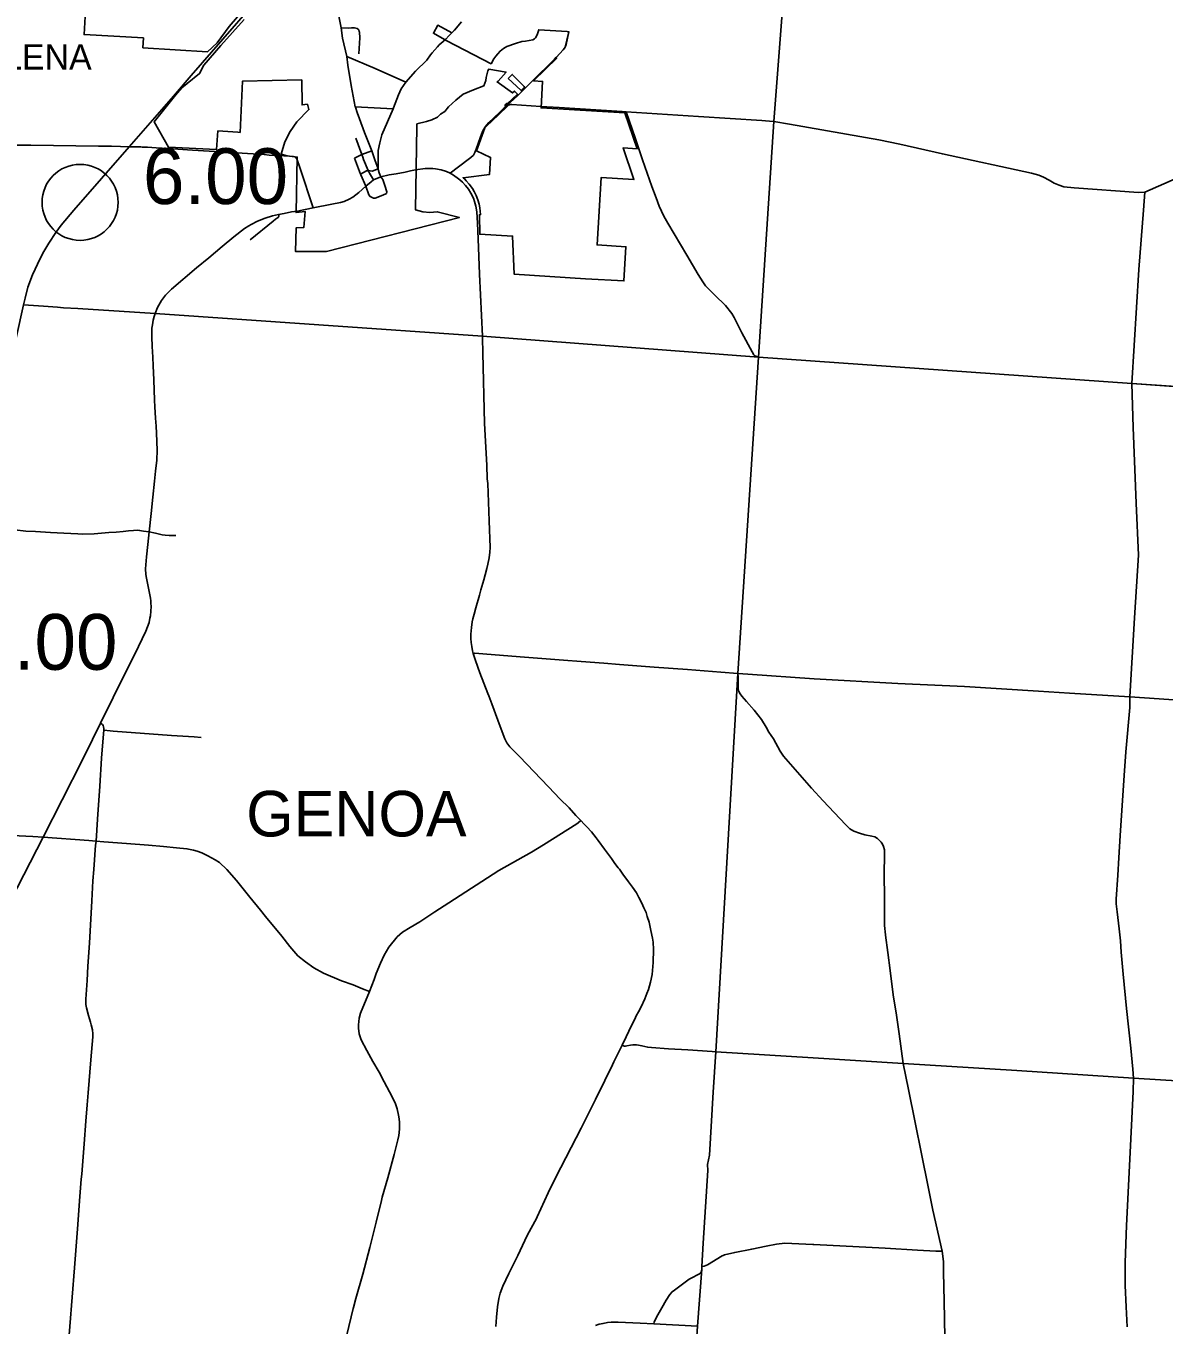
# Model space of a CAD drawing. Extents: x 1597222 to 1925846, y 496284 to 911751.
# Drawn here: x 1855559 to 1878005, y 784412 to 810051 of the extents above; entities that cross this region are included whole.
import ezdxf

# ---------------------------------------------------------------- set-up
doc = ezdxf.new("R2010")
doc.units = 0
for name, color, linetype in [('Default', 7, 'Continuous'), ('GM_X_City_Street', 7, 'Continuous'), ('GM_X_Corporation', 7, 'Continuous'), ('GM_X_Corporation_Text', 7, 'Continuous'), ('GM_X_County_Road', 7, 'Continuous'), ('GM_X_State_Route', 7, 'Continuous'), ('GM_X_Township', 7, 'Continuous'), ('GM_X_Township_Road', 7, 'Continuous'), ('GM_X_Township_Text', 7, 'Continuous')]:
    doc.layers.add(name, color=color, linetype=linetype)

msp = doc.modelspace()

# ---------------------------------------------------------------- linework, layer by layer
at = {"layer": 'Default'}
msp.add_circle((1856626, 806570), 750, dxfattribs=at)
at = {"layer": 'GM_X_City_Street'}
for points in [[(1862504, 807234), (1862441, 807407), (1862377, 807590), (1862238, 807946), (1862134, 808217), (1862091, 808342), (1862056, 808446), (1862054, 808456), (1861975, 808879), (1861910, 809276), (1861885, 809449), (1861803, 809811), (1861778, 810016), (1861699, 810418), (1861546, 811089), (1861463, 811523), (1861444, 811686), (1861392, 811897), (1861379, 812013)], [(1861778, 810016), (1861916, 810011), (1861980, 810012), (1862038, 810014), (1862092, 810003), (1862124, 809974), (1862131, 809944)], [(1862131, 809944), (1862131, 809942), (1862135, 809926), (1862141, 809820), (1862122, 809501)], [(1863675, 809639), (1863707, 809676), (1863789, 809745)], [(1861885, 809449), (1862443, 809212), (1863053, 808941)], [(1862505, 807272), (1862507, 807365), (1862505, 807463), (1862505, 807594), (1862537, 807743), (1862576, 807905), (1862799, 808414), (1862809, 808436), (1862905, 808695), (1862961, 808813), (1863053, 808941), (1863243, 809157), (1863465, 809379), (1863540, 809479)], [(1863540, 809479), (1863570, 809518), (1863675, 809639)], [(1865037, 808477), (1865260, 808682), (1865416, 808836), (1865533, 808954), (1865986, 809398), (1866019, 809433)], [(1862054, 808456), (1862799, 808414)], [(1865037, 808477), (1865069, 808490), (1865093, 808495), (1865114, 808499), (1865142, 808499), (1865716, 808463)], [(1862200, 807464), (1862183, 807513), (1862063, 807839)], [(1860865, 807468), (1860904, 807428), (1860965, 807236), (1861221, 806463)], [(1862038, 807445), (1862183, 807513), (1862377, 807590)], [(1862160, 807115), (1862155, 807127), (1862038, 807445)], [(1862337, 807144), (1862308, 807196), (1862215, 807419), (1862200, 807464)], [(1862155, 807127), (1862275, 807193), (1862300, 807195)], [(1862265, 806887), (1862160, 807115)], [(1862300, 807195), (1862308, 807196), (1862390, 807184), (1862504, 807234)], [(1862411, 807014), (1862337, 807144)], [(1862557, 807072), (1862524, 807153), (1862510, 807198), (1862504, 807234), (1862505, 807272)], [(1863145, 807190), (1863040, 807169), (1862861, 807136), (1862725, 807110), (1862557, 807072)], [(1861065, 806429), (1861221, 806463), (1861591, 806531), (1861760, 806564), (1861833, 806590), (1861930, 806630), (1862004, 806672), (1862127, 806763), (1862265, 806887), (1862364, 806976), (1862411, 807014), (1862557, 807072)], [(1862265, 806887), (1862322, 806718), (1862345, 806686), (1862414, 806654), (1862446, 806655), (1862598, 806709), (1862668, 806748)], [(1862668, 806748), (1862673, 806777), (1862638, 806904), (1862596, 807019), (1862557, 807072)]]:
    msp.add_lwpolyline(points, dxfattribs=at)
at = {"layer": 'GM_X_Corporation'}
for points in [[(1859933, 810468), (1859566, 810043), (1859327, 809721), (1859138, 809540), (1857865, 809621), (1857876, 809816), (1856704, 809881), (1856773, 811076)], [(1864151, 810133), (1864012, 809966), (1863958, 809914), (1863680, 810064), (1863595, 809906), (1863859, 809760), (1864733, 809304), (1864786, 809405), (1864823, 809458), (1864864, 809499), (1864909, 809555), (1864976, 809609), (1865042, 809648), (1865212, 809706), (1865339, 809742), (1865409, 809752), (1865553, 809778), (1865590, 809795), (1865610, 809820), (1865642, 809877), (1865672, 809975), (1866230, 809941), (1866265, 809936), (1866212, 809686), (1866193, 809633), (1866180, 809613), (1866156, 809577), (1866016, 809430), (1866027, 809418), (1865570, 808968), (1865749, 808958), (1865718, 808434), (1867372, 808337), (1867616, 807629), (1867336, 807644), (1867551, 807021), (1866904, 807063), (1866822, 805729), (1867392, 805693), (1867351, 805018), (1866597, 805063), (1865185, 805154), (1865155, 805904), (1864509, 805942), (1864501, 806327), (1864526, 806328), (1864512, 806460), (1864496, 806536), (1864471, 806620), (1864437, 806705), (1864397, 806785), (1864365, 806841), (1864301, 806929), (1864242, 806997), (1864212, 807027), (1864179, 807057), (1864703, 807122), (1864724, 807458), (1864445, 807587), (1864609, 808041), (1864644, 808074), (1864880, 808299), (1865062, 808472), (1865032, 808472), (1865006, 808488), (1865043, 808523), (1865057, 808523), (1865255, 808704), (1865245, 808714), (1865194, 808766), (1865155, 808731), (1864852, 808948), (1864871, 808960), (1865028, 809140), (1864686, 809196), (1864670, 809164), (1864633, 809031), (1864626, 808978), (1864590, 808873), (1864383, 808793), (1864180, 808703), (1864036, 808584), (1863894, 808456), (1863817, 808362), (1863732, 808311), (1863676, 808251), (1863563, 808196), (1863459, 808169), (1863269, 808119), (1863271, 808069), (1863240, 806424), (1863386, 806382), (1863526, 806367), (1863669, 806383), (1864106, 806273), (1861485, 805600), (1860876, 805597), (1860888, 806070), (1861038, 806073), (1861068, 806389), (1860885, 806368), (1860908, 807463), (1860893, 807463), (1860807, 807478), (1860713, 807490), (1860590, 807519), (1860665, 807762), (1860767, 807971), (1860900, 808159), (1861139, 808401), (1861111, 808506), (1861004, 808492), (1860999, 808987), (1859829, 808961), (1859781, 807951), (1859738, 807954), (1859344, 807980), (1859316, 807611), (1858367, 807661), (1858090, 808159), (1858507, 808685), (1858634, 808831), (1858740, 808916), (1858983, 809113), (1859065, 809276), (1859404, 809666), (1859863, 810176)]]:
    msp.add_lwpolyline(points, dxfattribs=at)
msp.add_lwpolyline([(1865072, 809017), (1865316, 808784), (1865324, 808776), (1865394, 808844), (1865384, 808855), (1865149, 809094)], close=True, dxfattribs=at)
at = {"layer": 'GM_X_County_Road'}
for points in [[(1863902, 809854), (1863958, 809914), (1864113, 810086)], [(1863789, 809745), (1863841, 809789), (1863902, 809854)], [(1863927, 807149), (1864283, 807418), (1864334, 807453), (1864387, 807502), (1864414, 807554), (1864439, 807622), (1864484, 807753), (1864542, 807914), (1864570, 807984), (1864606, 808050), (1864642, 808096), (1864687, 808146), (1864789, 808239), (1864902, 808347), (1864988, 808433), (1865037, 808477)], [(1865716, 808463), (1866076, 808441), (1867317, 808363), (1867396, 808359), (1868821, 808266), (1870074, 808188), (1870293, 808165)], [(1867396, 808359), (1867578, 807822), (1867722, 807411), (1867905, 806886), (1867988, 806661), (1868047, 806496), (1868091, 806398), (1868141, 806295), (1868218, 806162), (1868595, 805529), (1868820, 805149), (1868910, 805003), (1868961, 804924), (1869020, 804860), (1869146, 804736), (1869355, 804533), (1869481, 804376), (1869529, 804297), (1869678, 803996), (1869885, 803620), (1869914, 803562), (1869930, 803545)], [(1870293, 808165), (1870309, 808163), (1870615, 808110), (1872380, 807804), (1872796, 807716), (1873633, 807525), (1875394, 807147), (1875535, 807109), (1875625, 807069), (1875741, 807006), (1875837, 806950), (1875938, 806910), (1876028, 806878), (1876232, 806859), (1877504, 806767), (1877627, 806773), (1878001, 806934), (1879588, 807637)], [(1863927, 807149), (1863854, 807181), (1863750, 807215), (1863635, 807231), (1863584, 807238), (1863480, 807241), (1863432, 807239), (1863243, 807210), (1863145, 807190)], [(1864561, 803891), (1864561, 803926), (1864503, 805153), (1864476, 805850), (1864464, 806156), (1864453, 806381), (1864432, 806497), (1864406, 806587), (1864383, 806653), (1864335, 806753), (1864289, 806830), (1864225, 806905), (1864168, 806969), (1864116, 807017), (1864089, 807036), (1863994, 807108), (1863927, 807149)], [(1877369, 802994), (1877508, 805242), (1877600, 806419), (1877627, 806773)], [(1858107, 804378), (1858154, 804496), (1858234, 804633), (1858313, 804738), (1858376, 804801), (1858430, 804854), (1858924, 805276), (1859165, 805478), (1859431, 805702), (1859655, 805890), (1859866, 806052), (1859951, 806106), (1860001, 806134), (1860128, 806199), (1860275, 806259), (1860424, 806303), (1860542, 806330), (1860650, 806352), (1860797, 806382), (1860914, 806399), (1861033, 806421), (1861065, 806429)], [(1860542, 806330), (1860547, 806309), (1860546, 806295), (1860544, 806288), (1860541, 806283), (1860532, 806274), (1860517, 806262), (1860480, 806237), (1860436, 806200), (1859981, 805831)], [(1857028, 796294), (1857277, 796797), (1857775, 797801), (1857924, 798107), (1857985, 798279), (1858004, 798364), (1858012, 798409), (1858022, 798500), (1858025, 798592), (1858022, 798657), (1858018, 798708), (1858012, 798758), (1857995, 798858), (1857972, 798957), (1857933, 799154), (1857922, 799227), (1857914, 799334), (1857933, 799575), (1857961, 799815), (1857988, 800064), (1858027, 800427), (1858061, 800749), (1858095, 801069), (1858116, 801266), (1858139, 801481), (1858144, 801679), (1858131, 802013), (1858124, 802154), (1858116, 802308), (1858103, 802533), (1858096, 802669), (1858083, 803067), (1858070, 803343), (1858061, 803513), (1858050, 803726), (1858044, 803915), (1858041, 804015), (1858044, 804087), (1858051, 804150), (1858068, 804244), (1858087, 804316), (1858107, 804378)], [(1864668, 796879), (1864590, 797083), (1864513, 797287), (1864422, 797530), (1864380, 797664), (1864367, 797719), (1864351, 797802), (1864341, 797885), (1864336, 797962), (1864335, 798045), (1864343, 798179), (1864359, 798293), (1864372, 798348), (1864397, 798443), (1864431, 798566), (1864503, 798820), (1864532, 798925), (1864588, 799118), (1864615, 799218), (1864650, 799343), (1864671, 799432), (1864694, 799556), (1864707, 799664), (1864713, 799761), (1864693, 800283), (1864667, 801023), (1864657, 801114), (1864648, 801383), (1864604, 802208), (1864568, 803602), (1864561, 803891)], [(1869930, 803545), (1869936, 803538), (1870008, 803514), (1877369, 802994)], [(1877332, 796811), (1877420, 798367), (1877499, 799608), (1877454, 800633), (1877398, 802125), (1877369, 802994)], [(1854573, 800349), (1854755, 800266), (1854914, 800205), (1855015, 800169), (1855118, 800145), (1855340, 800109), (1855555, 800083), (1855746, 800073), (1856041, 800054), (1856308, 800043), (1856579, 800027), (1856677, 800021), (1856906, 800027), (1857196, 800056), (1857340, 800059), (1857473, 800073), (1857580, 800087), (1857682, 800095), (1857756, 800098), (1857798, 800096), (1857874, 800083), (1857988, 800064)], [(1857988, 800064), (1858110, 800041), (1858246, 800011), (1858305, 800003), (1858385, 799998), (1858516, 799994)], [(1869596, 797271), (1869264, 797299), (1868606, 797350), (1867949, 797398), (1867262, 797449), (1866957, 797476), (1866512, 797510), (1866160, 797537), (1865389, 797594), (1864651, 797652), (1864490, 797665), (1864412, 797670), (1864397, 797669), (1864380, 797664)], [(1872512, 792112), (1872490, 792299), (1872490, 792441), (1872490, 792557), (1872490, 792879), (1872488, 793281), (1872492, 793732), (1872489, 793791), (1872473, 793859), (1872454, 793904), (1872424, 793943), (1872389, 793984), (1872352, 794016), (1872303, 794045), (1872239, 794060), (1872103, 794090), (1871997, 794120), (1871888, 794161), (1871806, 794204), (1871722, 794290), (1871282, 794757), (1871051, 795010), (1870503, 795638), (1870435, 795737), (1870300, 795980), (1870212, 796114), (1870156, 796211), (1870067, 796366), (1869918, 796549), (1869770, 796721), (1869677, 796824), (1869643, 796870), (1869617, 796918), (1869609, 796940), (1869604, 796966), (1869603, 796991), (1869604, 797040), (1869606, 797200), (1869596, 797271)], [(1869596, 797271), (1869794, 797255), (1871103, 797168), (1872753, 797073), (1874071, 797014), (1875527, 796924), (1876143, 796885), (1877332, 796811)], [(1866503, 794368), (1866405, 794466), (1866272, 794620), (1866088, 794799), (1865870, 795027), (1865711, 795195), (1865579, 795328), (1865290, 795631), (1865178, 795747), (1865101, 795824), (1865042, 795902), (1865004, 795980), (1864969, 796070), (1864868, 796347), (1864745, 796675), (1864687, 796830), (1864668, 796879)], [(1877401, 789284), (1877390, 789464), (1877348, 789877), (1877267, 790662), (1877198, 791335), (1877163, 791768), (1877144, 791994), (1877118, 792235), (1877082, 792567), (1877064, 792727), (1877062, 792815), (1877091, 793291), (1877116, 793631), (1877141, 794076), (1877219, 795256), (1877251, 795728), (1877331, 796597), (1877332, 796811)], [(1877332, 796811), (1879735, 796644)], [(1851209, 784694), (1851326, 784936), (1852148, 786590), (1852443, 787187), (1853141, 788601), (1853675, 789667), (1853798, 789914), (1853979, 790280), (1854272, 790859), (1854392, 791103), (1854649, 791581), (1855260, 792799), (1855898, 794041), (1856273, 794777), (1856673, 795566), (1856869, 795971), (1857028, 796294)], [(1856946, 793960), (1856946, 793960), (1856971, 794394), (1857013, 795045), (1857051, 795598), (1857080, 796004), (1857092, 796153), (1857094, 796187), (1857090, 796216), (1857080, 796243), (1857067, 796263), (1857051, 796280), (1857028, 796294)], [(1862331, 790993), (1862331, 790993), (1862425, 791233), (1862464, 791347), (1862553, 791556), (1862621, 791712), (1862718, 791870), (1862878, 792073), (1862988, 792163), (1863137, 792257), (1863326, 792369), (1863622, 792566), (1863901, 792746), (1864887, 793380), (1865528, 793748), (1865763, 793892), (1866421, 794305), (1866453, 794326), (1866503, 794368)], [(1867241, 793436), (1867175, 793524), (1867110, 793619), (1866968, 793805), (1866845, 793974), (1866805, 794027), (1866710, 794146), (1866624, 794245), (1866569, 794300), (1866503, 794368)], [(1856379, 783803), (1856513, 785538), (1856582, 786399), (1856616, 786866), (1856649, 787292), (1856657, 787391), (1856707, 787988), (1856742, 788435), (1856768, 788759), (1856787, 788996), (1856839, 789647), (1856877, 790103), (1856879, 790157), (1856870, 790238), (1856843, 790340), (1856828, 790389), (1856789, 790519), (1856749, 790673), (1856741, 790738), (1856737, 790808), (1856738, 790844), (1856763, 791215), (1856781, 791498), (1856809, 791946), (1856855, 792786), (1856879, 793181), (1856895, 793405), (1856933, 793880), (1856936, 793913), (1856946, 793960)], [(1867153, 789604), (1867200, 789700), (1867319, 789935), (1867396, 790101), (1867504, 790327), (1867565, 790450), (1867596, 790512), (1867641, 790592), (1867690, 790690), (1867763, 790847), (1867804, 790955), (1867838, 791037), (1867877, 791180), (1867910, 791333), (1867929, 791569), (1867933, 791826), (1867927, 791967), (1867917, 792047), (1867886, 792196), (1867849, 792363), (1867813, 792478), (1867788, 792552), (1867745, 792648), (1867704, 792736), (1867647, 792848), (1867599, 792941), (1867524, 793055), (1867442, 793157), (1867330, 793312), (1867263, 793407), (1867241, 793436)], [(1873682, 784168), (1873669, 784889), (1873663, 785162), (1873657, 785466), (1873655, 785664), (1873627, 785869), (1873446, 786682), (1873351, 787142), (1872964, 789059), (1872863, 789571), (1872778, 790159), (1872727, 790526), (1872666, 790930), (1872604, 791411), (1872559, 791766), (1872513, 792107), (1872512, 792112)], [(1862860, 787938), (1862891, 788070), (1862911, 788154), (1862924, 788278), (1862924, 788410), (1862919, 788484), (1862909, 788555), (1862881, 788678), (1862846, 788780), (1862782, 788915), (1862621, 789214), (1862525, 789400), (1862401, 789615), (1862280, 789828), (1862168, 790041), (1862129, 790158), (1862118, 790274), (1862114, 790336), (1862129, 790467), (1862155, 790566), (1862331, 790993)], [(1865634, 786531), (1865642, 786548), (1865861, 787020), (1866012, 787331), (1866508, 788298), (1866790, 788861), (1866977, 789237), (1867126, 789549), (1867153, 789604)], [(1872863, 789571), (1875101, 789435), (1877401, 789284), (1879855, 789132), (1880616, 789098), (1881806, 789028), (1882295, 788997), (1882567, 788975)], [(1877278, 784375), (1877260, 784771), (1877240, 785195), (1877237, 785645), (1877265, 786378), (1877326, 787557), (1877396, 789022), (1877401, 789284)], [(1861455, 782568), (1861484, 782698), (1861529, 782870), (1861693, 783500), (1861750, 783702), (1861886, 784220), (1862013, 784736), (1862018, 784757), (1862066, 784939), (1862201, 785417), (1862338, 785941), (1862465, 786443), (1862569, 786870), (1862577, 786904), (1862585, 786934), (1862693, 787317), (1862818, 787780), (1862854, 787912), (1862860, 787938)], [(1864829, 784383), (1864841, 784568), (1864856, 784770), (1864885, 784933), (1864914, 785038), (1864961, 785176), (1865080, 785426), (1865258, 785787), (1865446, 786179), (1865634, 786531)], [(1868806, 784389), (1867942, 784436), (1867676, 784450), (1867236, 784472), (1867100, 784466), (1867030, 784459), (1866941, 784445), (1866864, 784426), (1866789, 784401)]]:
    msp.add_lwpolyline(points, dxfattribs=at)
at = {"layer": 'GM_X_State_Route'}
msp.add_lwpolyline([(1853225, 794338), (1854573, 800349), (1855512, 804546), (1855541, 804679), (1855596, 804898), (1855689, 805139), (1855836, 805465), (1855908, 805599), (1856008, 805767), (1856148, 805978), (1856255, 806119), (1856504, 806413), (1857597, 807668), (1858467, 808668), (1858818, 809072), (1859440, 809788), (1860025, 810459)], dxfattribs=at)
at = {"layer": 'GM_X_Township'}
for points in [[(1896867, 801714), (1892288, 802025), (1891297, 802083), (1891221, 802088), (1891165, 802089), (1883392, 802588), (1877369, 802994), (1870008, 803514), (1870309, 808163), (1870779, 814239)], [(1855512, 804546), (1855904, 804520), (1856177, 804502), (1856300, 804491), (1856579, 804475), (1858107, 804378), (1864561, 803926), (1870008, 803514), (1869596, 797271), (1869163, 789806), (1869111, 789007), (1869039, 787768), (1869000, 787580), (1869008, 787459), (1868914, 786029), (1868892, 785569), (1868890, 785515), (1868806, 784389), (1868751, 783613), (1868734, 783178), (1868439, 777975), (1868321, 776001)]]:
    msp.add_lwpolyline(points, dxfattribs=at)
at = {"layer": 'GM_X_Township_Road'}
for points in [[(1866019, 809433), (1866023, 809436), (1866156, 809577), (1866193, 809633), (1866260, 809906), (1866263, 809939)], [(1853175, 807697), (1854218, 807699), (1855651, 807697), (1856991, 807682), (1857244, 807678), (1857423, 807675), (1857597, 807668)], [(1857597, 807668), (1857597, 807668), (1857824, 807663), (1857853, 807662)], [(1857853, 807662), (1857956, 807657), (1858128, 807649), (1858365, 807634), (1858840, 807601), (1860259, 807513), (1860357, 807502), (1860647, 807487), (1860662, 807487)], [(1860662, 807487), (1860682, 807486), (1860759, 807481), (1860834, 807473), (1860865, 807468)], [(1855512, 804546), (1855904, 804520), (1856177, 804502), (1856300, 804491), (1856579, 804475), (1858107, 804378)], [(1877369, 802994), (1880691, 802757), (1883392, 802588)], [(1857092, 796153), (1857218, 796138), (1857278, 796132), (1858429, 796050), (1858876, 796019), (1859017, 796010)], [(1853911, 794167), (1854809, 794108), (1855052, 794090), (1855289, 794075), (1855696, 794051), (1855898, 794041), (1856800, 793974), (1856946, 793960)], [(1856946, 793960), (1857092, 793949), (1857542, 793914), (1857978, 793881), (1858274, 793854), (1858527, 793830), (1858733, 793811), (1858865, 793782), (1858933, 793763), (1859024, 793732), (1859146, 793672), (1859290, 793592), (1859376, 793539), (1859523, 793403), (1859714, 793187), (1859975, 792860), (1860182, 792601), (1860283, 792472), (1860603, 792087), (1860762, 791885), (1860922, 791702), (1861069, 791579), (1861235, 791461), (1861427, 791357), (1861779, 791208), (1862012, 791128), (1862197, 791047), (1862331, 790993)], [(1867319, 789935), (1867341, 789922), (1867365, 789918), (1867384, 789918), (1867408, 789922), (1867479, 789935), (1867531, 789940), (1867600, 789940), (1867638, 789937), (1867706, 789923), (1867821, 789895), (1867896, 789887), (1868229, 789864), (1868613, 789842), (1869090, 789811)], [(1869090, 789811), (1869163, 789806), (1871085, 789686), (1872863, 789571)], [(1868892, 785569), (1868914, 786029), (1869008, 787459), (1869000, 787580), (1869039, 787768), (1869111, 789007)], [(1869311, 785786), (1869335, 785796), (1869538, 785844), (1869873, 785912), (1870158, 785969), (1870363, 786009), (1870524, 786025), (1871080, 786004), (1871097, 786003)], [(1871097, 786003), (1872502, 785926), (1873145, 785890), (1873503, 785869), (1873627, 785869)], [(1868891, 785527), (1868892, 785569), (1868902, 785570)], [(1868902, 785570), (1868932, 785574), (1869001, 785603), (1869292, 785779), (1869311, 785786)], [(1867942, 784436), (1867949, 784478), (1868023, 784612), (1868101, 784749), (1868183, 784905), (1868256, 785017), (1868303, 785069), (1868353, 785099), (1868641, 785317), (1868679, 785339), (1868830, 785413), (1868860, 785439), (1868876, 785462), (1868890, 785515), (1868891, 785527)]]:
    msp.add_lwpolyline(points, dxfattribs=at)

# ---------------------------------------------------------------- texts
at = {"layer": 'Default'}
for s, p in [('6.00', (1857866, 806537)), ('4.00', (1854500, 797345))]:
    msp.add_text(s, height=1100, dxfattribs=at).set_placement(p)
at = {"layer": 'GM_X_Corporation_Text'}
msp.add_text('GALENA', height=500, rotation=0, dxfattribs=at).set_placement((1854142, 809190))
at = {"layer": 'GM_X_Township_Text'}
msp.add_text('GENOA', height=900, rotation=0, dxfattribs=at).set_placement((1859903, 794055))

doc.saveas('drawing.dxf')
